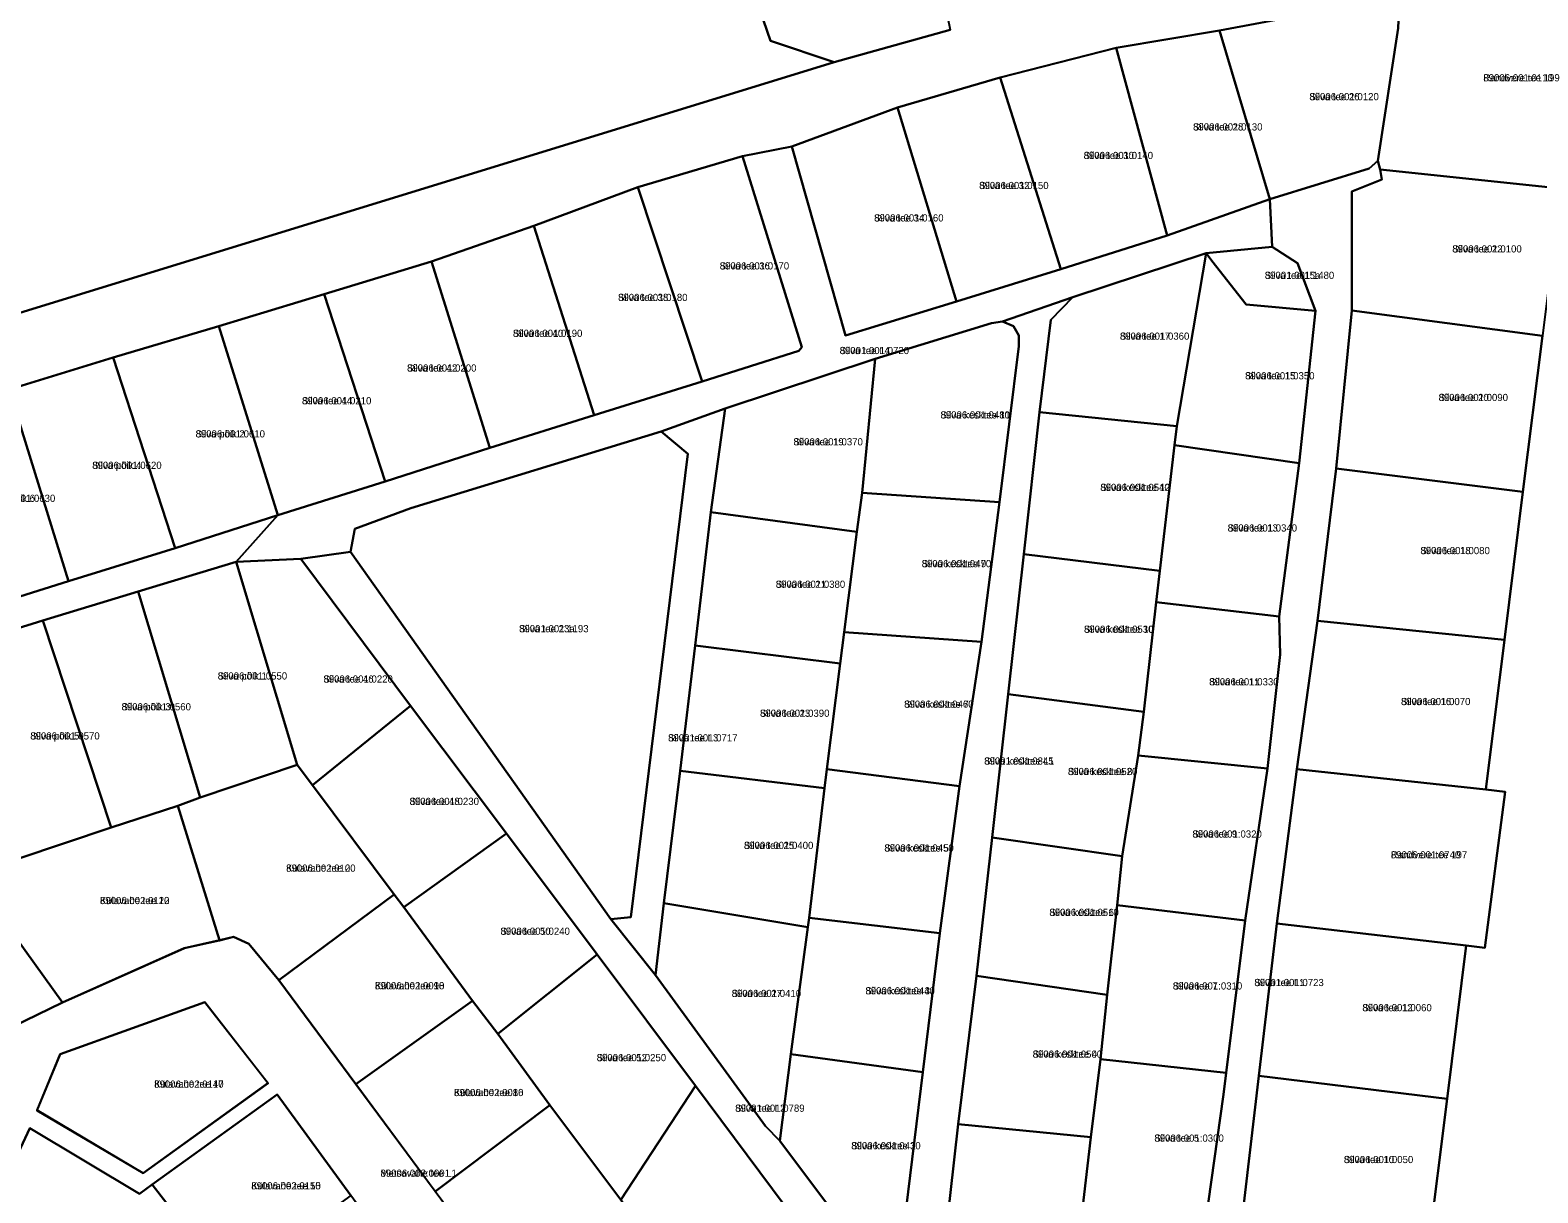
# Model space of a CAD drawing. Extents: x 526849 to 562296, y 6591741 to 6618546.
# Drawn here: x 550900.4 to 551215.3, y 6596298.2 to 6596541 of the extents above; entities that cross this region are included whole.
import ezdxf

# ---------------------------------------------------------------- set-up
doc = ezdxf.new("R2010")
doc.units = 0
for name, color, linetype in [('L_AADRESS', 7, 'Continuous'), ('PIIR', 7, 'Continuous'), ('TUNNUS', 7, 'Continuous')]:
    doc.layers.add(name, color=color, linetype=linetype)

msp = doc.modelspace()

# ---------------------------------------------------------------- linework, layer by layer
at = {"layer": 'PIIR'}
for points in [[(550502.84, 6596513.86), (550540.75, 6596522.24), (550580.98, 6596531.14), (550618.45, 6596539.43), (550657.91, 6596548.15), (550700.15, 6596557.5), (550724.96, 6596562.98), (550747.13, 6596567.89), (550790.4, 6596577.45), (550843.93, 6596589.29), (550876.6, 6596596.52), (550922.92, 6596606.76), (551006.9, 6596625.33), (551024.02, 6596629.12), (551028, 6596617.5), (551037.81, 6596588.91), (551046.33, 6596564.08), (551055.02, 6596538.73), (551068.28, 6596534.32), (550552.36, 6596375.52), (550533.68, 6596374.18), (550516.36, 6596378.66)], [(551046.33, 6596564.08), (551086.16, 6596571.97), (551092.5, 6596541.03), (551068.28, 6596534.32), (551055.02, 6596538.73)], [(551181.87, 6596513.7), (551186.1, 6596541.41), (551186.33, 6596547.98), (551225.89, 6596554.71), (551220.04, 6596507.9), (551182.35, 6596511.92)], [(551148.76, 6596540.93), (551186.33, 6596547.98), (551186.1, 6596541.41), (551181.87, 6596513.7), (551180.01, 6596512.11), (551159.29, 6596505.68)], [(551127.22, 6596537.3), (551148.76, 6596540.93), (551159.29, 6596505.68), (551137.82, 6596498.14)], [(551102.96, 6596531.08), (551127.22, 6596537.3), (551137.82, 6596498.14), (551115.63, 6596491.07)], [(551081.53, 6596524.81), (551102.96, 6596531.08), (551115.63, 6596491.07), (551093.86, 6596484.34)], [(551059.42, 6596516.7), (551081.53, 6596524.81), (551093.86, 6596484.34), (551070.69, 6596477.22)], [(551049.17, 6596514.64), (551059.42, 6596516.7), (551070.69, 6596477.22), (551093.86, 6596484.34), (551115.63, 6596491.07), (551137.82, 6596498.14), (551159.29, 6596505.68), (551159.79, 6596495.72), (551145.97, 6596494.4), (551118.15, 6596485.23), (551103.47, 6596480.15), (551101.15, 6596479.79), (551076.86, 6596472.34), (551045.55, 6596461.98), (551032.14, 6596457.18), (550979.88, 6596441.18), (550968.18, 6596436.89), (550967.28, 6596432.04), (550956.94, 6596430.62), (550943.43, 6596429.98), (550952.14, 6596439.69), (550974.5, 6596446.77), (550996.41, 6596453.74), (551018.2, 6596460.61), (551040.74, 6596467.62), (551060.95, 6596474.04), (551061.53, 6596474.78)], [(551027.26, 6596508.23), (551049.17, 6596514.64), (551061.53, 6596474.78), (551060.95, 6596474.04), (551040.74, 6596467.62)], [(551176.38, 6596507.32), (551182.64, 6596509.8), (551182.35, 6596511.92), (551220.04, 6596507.9), (551216.21, 6596477.19), (551176.41, 6596482.46)], [(551005.59, 6596500.12), (551027.26, 6596508.23), (551040.74, 6596467.62), (551018.2, 6596460.61)], [(550984.22, 6596492.71), (551005.59, 6596500.12), (551018.2, 6596460.61), (550996.41, 6596453.74)], [(551139.87, 6596458.29), (551111.17, 6596461.22), (551113.52, 6596480.49), (551118.15, 6596485.23), (551145.97, 6596494.4)], [(551139.87, 6596458.29), (551145.97, 6596494.4), (551147.19, 6596492.82), (551154.31, 6596483.69), (551168.84, 6596482.36), (551165.4, 6596450.57), (551139.4, 6596454.36)], [(551165.07, 6596492.36), (551168.84, 6596482.36), (551154.31, 6596483.69), (551147.19, 6596492.82), (551145.97, 6596494.4), (551159.79, 6596495.72)], [(550961.78, 6596485.84), (550984.22, 6596492.71), (550996.41, 6596453.74), (550974.5, 6596446.77)], [(550939.77, 6596479.14), (550961.78, 6596485.84), (550974.5, 6596446.77), (550952.14, 6596439.69)], [(551088.82, 6596266.44), (551081.09, 6596276.84), (551086.78, 6596323.41), (551090.37, 6596352.42), (551094.47, 6596383.11), (551099.07, 6596413.26), (551102.79, 6596442.45), (551106.83, 6596474.98), (551106.84, 6596477.21), (551105.78, 6596479.14), (551103.47, 6596480.15), (551118.15, 6596485.23), (551113.52, 6596480.49), (551111.17, 6596461.22), (551107.89, 6596431.54), (551104.66, 6596402.32), (551101.26, 6596372.44), (551098.05, 6596343.54), (551094.2, 6596312.54), (551090.95, 6596283.39), (551090.58, 6596281.58)], [(551176.41, 6596482.46), (551216.21, 6596477.19), (551212.14, 6596444.61), (551173.15, 6596449.44)], [(550917.7, 6596472.6), (550939.77, 6596479.14), (550952.14, 6596439.69), (550930.68, 6596432.81)], [(551101.15, 6596479.79), (551103.47, 6596480.15), (551105.78, 6596479.14), (551106.84, 6596477.21), (551106.83, 6596474.98), (551102.79, 6596442.45), (551074.16, 6596444.38), (551076.86, 6596472.34)], [(550896.01, 6596465.94), (550917.7, 6596472.6), (550930.68, 6596432.81), (550908.36, 6596425.95)], [(551045.55, 6596461.98), (551076.86, 6596472.34), (551074.16, 6596444.38), (551073.02, 6596436.22), (551042.52, 6596440.34)], [(550873.91, 6596459.07), (550896.01, 6596465.94), (550908.36, 6596425.95), (550886.67, 6596419.12)], [(551032.14, 6596457.18), (551045.55, 6596461.98), (551042.52, 6596440.34), (551039.26, 6596412.53), (551036.13, 6596386.31), (551032.74, 6596358.73), (551031, 6596343.64), (551021.67, 6596355.39), (551025.83, 6596355.76), (551037.71, 6596452.53)], [(551107.89, 6596431.54), (551111.17, 6596461.22), (551139.87, 6596458.29), (551139.4, 6596454.36), (551136.29, 6596428.1)], [(551025.83, 6596355.76), (551021.67, 6596355.39), (550967.28, 6596432.04), (550968.18, 6596436.89), (550979.88, 6596441.18), (551032.14, 6596457.18), (551037.71, 6596452.53)], [(551161.21, 6596418.58), (551135.55, 6596421.56), (551136.29, 6596428.1), (551139.4, 6596454.36), (551165.4, 6596450.57)], [(551173.15, 6596449.44), (551212.14, 6596444.61), (551208.28, 6596413.69), (551169.24, 6596417.68)], [(551099.07, 6596413.26), (551070.37, 6596415.28), (551073.02, 6596436.22), (551074.16, 6596444.38), (551102.79, 6596442.45)], [(550943.43, 6596429.98), (550922.93, 6596423.75), (550903.03, 6596417.71), (550883.52, 6596411.68), (550864.45, 6596405.6), (550830.39, 6596395.11), (550838.18, 6596371.91), (550838.2, 6596364.32), (550830.73, 6596370.47), (550822.31, 6596394.91), (550820.95, 6596398.4), (550825.97, 6596400.03), (550842.82, 6596405.22), (550864.71, 6596411.95), (550886.67, 6596419.12), (550908.36, 6596425.95), (550930.68, 6596432.81), (550952.14, 6596439.69)], [(551042.52, 6596440.34), (551073.02, 6596436.22), (551070.37, 6596415.28), (551069.54, 6596408.73), (551039.26, 6596412.53)], [(551134.17, 6596193.13), (551123.33, 6596207.83), (551104.41, 6596233.29), (551085.18, 6596259), (551066.23, 6596284.49), (551039.33, 6596320.56), (551018.77, 6596347.97), (550999.86, 6596373.25), (550979.83, 6596399.91), (550956.94, 6596430.62), (550967.28, 6596432.04), (551021.67, 6596355.39), (551031, 6596343.64), (551053.96, 6596312.14), (551056.93, 6596309.07), (551081.09, 6596276.84), (551088.82, 6596266.44), (551111.95, 6596235.1), (551120.32, 6596223.51), (551138.3, 6596224.47)], [(551104.66, 6596402.32), (551107.89, 6596431.54), (551136.29, 6596428.1), (551135.55, 6596421.56), (551132.96, 6596398.68)], [(550922.93, 6596423.75), (550943.43, 6596429.98), (550956.17, 6596387.56), (550935.88, 6596380.75)], [(550956.17, 6596387.56), (550943.43, 6596429.98), (550956.94, 6596430.62), (550979.83, 6596399.91), (550959.35, 6596383.32)], [(550903.03, 6596417.71), (550922.93, 6596423.75), (550935.88, 6596380.75), (550931.24, 6596379.03), (550917.28, 6596374.5)], [(551161.43, 6596410.59), (551158.81, 6596386.84), (551131.78, 6596389.55), (551132.96, 6596398.68), (551135.55, 6596421.56), (551161.21, 6596418.58)], [(550883.52, 6596411.68), (550903.03, 6596417.71), (550917.28, 6596374.5), (550897.8, 6596367.96)], [(551169.24, 6596417.68), (551208.28, 6596413.69), (551204.38, 6596382.42), (551164.9, 6596386.71)], [(551039.26, 6596412.53), (551069.54, 6596408.73), (551066.76, 6596386.71), (551066.25, 6596382.68), (551036.13, 6596386.31)], [(551094.47, 6596383.11), (551066.76, 6596386.71), (551069.54, 6596408.73), (551070.37, 6596415.28), (551099.07, 6596413.26)], [(550976.43, 6596360.53), (550959.35, 6596383.32), (550979.83, 6596399.91), (550999.86, 6596373.25), (550978.43, 6596357.83)], [(551104.66, 6596402.32), (551132.96, 6596398.68), (551131.78, 6596389.55), (551128.44, 6596368.53), (551101.26, 6596372.44)], [(550956.17, 6596387.56), (550959.35, 6596383.32), (550976.43, 6596360.53), (550952.34, 6596342.65), (550946.05, 6596350.22), (550942.86, 6596351.69), (550939.92, 6596350.94), (550931.24, 6596379.03), (550935.88, 6596380.75)], [(551154.15, 6596355.05), (551127.4, 6596358.25), (551128.44, 6596368.53), (551131.78, 6596389.55), (551158.81, 6596386.84)], [(551036.13, 6596386.31), (551066.25, 6596382.68), (551063.08, 6596355.65), (551062.79, 6596353.71), (551032.74, 6596358.73)], [(551090.37, 6596352.42), (551063.08, 6596355.65), (551066.25, 6596382.68), (551066.76, 6596386.71), (551094.47, 6596383.11)], [(551204.38, 6596382.42), (551208.44, 6596381.96), (551204.16, 6596349.4), (551200.31, 6596349.87), (551160.77, 6596354.44), (551164.9, 6596386.71)], [(550931.24, 6596379.03), (550939.92, 6596350.94), (550932.57, 6596349.27), (550907.15, 6596337.96), (550887.9, 6596364.63), (550897.8, 6596367.96), (550917.28, 6596374.5)], [(550978.43, 6596357.83), (550999.86, 6596373.25), (551018.77, 6596347.97), (550998.07, 6596331.41), (550992.75, 6596338.3)], [(551098.05, 6596343.54), (551101.26, 6596372.44), (551128.44, 6596368.53), (551127.4, 6596358.25), (551125.3, 6596339.59)], [(550887.9, 6596364.63), (550907.15, 6596337.96), (550888.88, 6596329.1), (550870.76, 6596323.96), (550860.24, 6596355.35), (550878.68, 6596361.7)], [(550992.75, 6596338.3), (550968.4, 6596320.88), (550952.34, 6596342.65), (550976.43, 6596360.53), (550978.43, 6596357.83)], [(551053.96, 6596312.14), (551031, 6596343.64), (551032.74, 6596358.73), (551062.79, 6596353.71), (551059.27, 6596327.14), (551056.93, 6596309.07)], [(551090.37, 6596352.42), (551086.78, 6596323.41), (551059.27, 6596327.14), (551062.79, 6596353.71), (551063.08, 6596355.65)], [(551150.15, 6596323.24), (551123.89, 6596326.11), (551125.3, 6596339.59), (551127.4, 6596358.25), (551154.15, 6596355.05)], [(551160.77, 6596354.44), (551200.31, 6596349.87), (551196.31, 6596317.83), (551156.99, 6596322.63)], [(551018.77, 6596347.97), (551039.33, 6596320.56), (551023.76, 6596296.72), (551008.93, 6596316.55), (550998.07, 6596331.41)], [(551094.2, 6596312.54), (551098.05, 6596343.54), (551125.3, 6596339.59), (551123.89, 6596326.11), (551121.93, 6596309.83)], [(550906.66, 6596327.2), (550901.79, 6596315.41), (550924, 6596302.3), (550950.04, 6596321.13), (550936.86, 6596338.03)], [(550936.86, 6596338.04), (550950.08, 6596321.09), (550924.01, 6596302.3), (550901.81, 6596315.45), (550906.64, 6596327.19)], [(551008.93, 6596316.55), (550984.95, 6596298.52), (550968.4, 6596320.88), (550992.75, 6596338.3), (550998.07, 6596331.41)], [(551081.09, 6596276.84), (551056.93, 6596309.07), (551059.27, 6596327.14), (551086.78, 6596323.41)], [(551149.59, 6596318.78), (551145.77, 6596291.52), (551120.19, 6596294.88), (551121.93, 6596309.83), (551123.89, 6596326.11), (551150.15, 6596323.24)], [(551156.99, 6596322.63), (551196.31, 6596317.83), (551192.37, 6596286.22), (551153.2, 6596290.55)], [(550806.79, 6596277.8), (550806.2, 6596260.48), (550850.99, 6596252.41), (550884.4, 6596246.39), (550914.38, 6596240.89), (550917.47, 6596238.7), (550925.48, 6596233.16), (550958.22, 6596256.98), (550983.56, 6596275.41), (550967.38, 6596297.69), (550951.96, 6596318.74), (550925.84, 6596299.94), (550923.21, 6596298.04), (550900.3, 6596311.7), (550897.38, 6596305.47), (550894.68, 6596306.3), (550885.81, 6596312.96), (550875.33, 6596310), (550842.72, 6596295.97)], [(550936.69, 6596285.88), (550925.87, 6596299.93), (550951.95, 6596318.75), (550967.38, 6596297.69), (550941.86, 6596279.11)], [(551023.76, 6596296.72), (551039.33, 6596320.56), (551066.23, 6596284.49), (551044.34, 6596268.92), (551026.95, 6596292.39)], [(551026.95, 6596292.39), (551002.78, 6596274.49), (550984.95, 6596298.52), (551008.93, 6596316.55), (551023.76, 6596296.72)], [(550842.72, 6596295.97), (550875.33, 6596310), (550885.81, 6596312.96), (550894.68, 6596306.3), (550897.38, 6596305.47), (550900.3, 6596311.7), (550923.21, 6596298.04), (550925.84, 6596299.94), (550936.69, 6596285.87), (550927.35, 6596279.09), (550890.53, 6596280.37), (550857.07, 6596285.92)], [(551090.95, 6596283.39), (551094.2, 6596312.54), (551121.93, 6596309.83), (551120.19, 6596294.88), (551118.49, 6596279.69)]]:
    msp.add_lwpolyline(points, close=True, dxfattribs=at)
for points in [[(551186.33, 6596547.98), (551148.76, 6596540.93), (551127.22, 6596537.3), (551102.96, 6596531.08), (551081.53, 6596524.81), (551059.42, 6596516.7), (551049.17, 6596514.64), (551027.26, 6596508.23), (551005.59, 6596500.12), (550984.22, 6596492.71), (550961.78, 6596485.84), (550939.77, 6596479.14), (550917.7, 6596472.6), (550896.01, 6596465.94), (550873.91, 6596459.07), (550851.8, 6596452.33), (550829.76, 6596445.49), (550807.86, 6596438.64), (550784.34, 6596431.16), (550695.5, 6596403.25), (550540.54, 6596354.46)], [(550552.36, 6596375.52), (551068.28, 6596534.32), (551092.5, 6596541.03)], [(551145.77, 6596291.52), (551149.59, 6596318.78), (551150.15, 6596323.24), (551154.15, 6596355.05), (551158.81, 6596386.84), (551161.43, 6596410.59), (551161.21, 6596418.58), (551165.4, 6596450.57), (551168.84, 6596482.36), (551165.07, 6596492.36), (551159.79, 6596495.72), (551159.29, 6596505.68), (551180.01, 6596512.11), (551181.87, 6596513.7), (551182.35, 6596511.92), (551182.64, 6596509.8), (551176.38, 6596507.32), (551176.41, 6596482.46), (551173.15, 6596449.44), (551169.24, 6596417.68), (551164.9, 6596386.71), (551160.77, 6596354.44), (551156.99, 6596322.63), (551153.2, 6596290.55)], [(551157.47, 6596029.7), (551165.04, 6596077.7), (551168.89, 6596078.24), (551171.19, 6596097.74), (551168.74, 6596101.05), (551156.07, 6596118.25), (551148.73, 6596128.3), (551155, 6596133.16), (551172.69, 6596128.6), (551180.25, 6596189.15), (551184.46, 6596222.92), (551188.41, 6596254.51), (551192.37, 6596286.22), (551196.31, 6596317.83), (551200.31, 6596349.87), (551204.16, 6596349.4), (551208.44, 6596381.96), (551204.38, 6596382.42), (551208.28, 6596413.69), (551212.14, 6596444.61), (551216.21, 6596477.19)], [(550888.88, 6596329.1), (550907.15, 6596337.96), (550932.58, 6596349.28), (550939.91, 6596350.93), (550942.86, 6596351.69), (550946.04, 6596350.21), (550952.34, 6596342.65), (550968.41, 6596320.88), (550984.94, 6596298.54), (551002.76, 6596274.5)]]:
    msp.add_lwpolyline(points, dxfattribs=at)

# ---------------------------------------------------------------- texts
at = {"layer": 'L_AADRESS'}
for s, p in [('Randvere tee 199', (551203.88, 6596530.29)), ('Silva tee 26', (551167.54, 6596526.35)), ('Silva tee 28', (551143.25, 6596520.03)), ('Silva tee 30', (551120.39, 6596514.07)), ('Silva tee 32', (551098.58, 6596507.8)), ('Silva tee 34', (551076.64, 6596501.03)), ('Silva tee 22', (551197.39, 6596494.56)), ('Silva tee 36', (551044.39, 6596491.01)), ('Silva tee 15a', (551158.23, 6596489.04)), ('Silva tee 38', (551023.17, 6596484.43)), ('Silva tee 40', (551001.21, 6596476.93)), ('Silva tee 17', (551127.97, 6596476.34)), ('Silva tee L4', (551069.43, 6596473.34)), ('Silva tee 42', (550979.09, 6596469.69)), ('Silva tee 15', (551154.12, 6596468.07)), ('Silva tee 44', (550957.14, 6596462.85)), ('Silva tee 20', (551194.52, 6596463.54)), ('Silva kesktee 11', (551090.5, 6596459.9)), ('Silva põik 2', (550934.92, 6596455.94)), ('Silva tee 19', (551059.79, 6596454.28)), ('Silva põik 4', (550913.34, 6596449.37)), ('Silva põik 6', (550891.13, 6596442.48)), ('Silva kesktee 12', (551123.88, 6596444.76)), ('Silva tee 13', (551150.47, 6596436.29)), ('Silva tee 18', (551190.73, 6596431.57)), ('Silva kesktee 9', (551086.58, 6596428.84)), ('Silva tee 21', (551056.1, 6596424.54)), ('Silva tee 23a', (551002.5, 6596415.26)), ('Silva kesktee 10', (551120.47, 6596415.15)), ('Silva põik 1', (550939.55, 6596405.39)), ('Silva tee 46', (550961.63, 6596404.75)), ('Silva tee 11', (551146.61, 6596404.17)), ('Silva põik 3', (550919.46, 6596398.95)), ('Silva kesktee 7', (551082.91, 6596399.5)), ('Silva tee 16', (551186.67, 6596400.05)), ('Silva tee 23', (551052.81, 6596397.61)), ('Silva põik 5', (550900.4, 6596392.87)), ('Silva tee L3', (551033.61, 6596392.47)), ('Silva kesktee L1', (551099.62, 6596387.63)), ('Silva kesktee 8', (551117.11, 6596385.44)), ('Silva tee 48', (550979.61, 6596379.2)), ('Silva tee 25', (551049.45, 6596370.01)), ('Silva tee 9', (551143.11, 6596372.39)), ('Silva kesktee 5', (551078.77, 6596369.47)), ('Randvere tee 197', (551184.56, 6596368.05)), ('Külavahe tee 20', (550953.84, 6596365.27)), ('Külavahe tee 22', (550914.96, 6596358.5)), ('Silva kesktee 6', (551113.24, 6596356.03)), ('Silva tee 50', (550998.6, 6596352.09)), ('Külavahe tee 18', (550972.38, 6596340.71)), ('Silva tee 27', (551046.89, 6596339.1)), ('Silva kesktee 3', (551074.82, 6596339.65)), ('Silva tee 7', (551139.02, 6596340.66)), ('Silva tee L1', (551156.05, 6596341.38)), ('Silva tee 12', (551178.6, 6596336.13)), ('Silva kesktee 4', (551109.75, 6596326.43)), ('Silva tee 52', (551018.7, 6596325.7)), ('Külavahe tee 17', (550926.28, 6596320.17)), ('Külavahe tee 16', (550988.9, 6596318.41)), ('Silva tee L2', (551047.62, 6596315.14)), ('Silva kesktee 1', (551071.86, 6596307.3)), ('Silva tee 5', (551135.17, 6596308.89)), ('Silva tee 10', (551174.74, 6596304.42)), ('Metsavahe tee L1', (550973.55, 6596301.57)), ('Külavahe tee 15', (550946.56, 6596298.93))]:
    msp.add_text(s, height=1.5, dxfattribs=at).set_placement(p)
at = {"layer": 'TUNNUS'}
for s, p in [('89006:001:0110', (551203.88, 6596530.29)), ('89006:001:0120', (551167.54, 6596526.35)), ('89006:001:0130', (551143.25, 6596520.03)), ('89006:001:0140', (551120.39, 6596514.07)), ('89006:001:0150', (551098.58, 6596507.8)), ('89006:001:0160', (551076.64, 6596501.03)), ('89006:001:0100', (551197.39, 6596494.56)), ('89006:001:0170', (551044.39, 6596491.01)), ('89001:001:1480', (551158.23, 6596489.04)), ('89006:001:0180', (551023.17, 6596484.43)), ('89006:001:0190', (551001.21, 6596476.93)), ('89006:001:0360', (551127.97, 6596476.34)), ('89001:001:0720', (551069.43, 6596473.34)), ('89006:001:0200', (550979.09, 6596469.69)), ('89006:001:0350', (551154.12, 6596468.07)), ('89006:001:0210', (550957.14, 6596462.85)), ('89006:001:0090', (551194.52, 6596463.54)), ('89006:001:0480', (551090.5, 6596459.9)), ('89006:001:0610', (550934.92, 6596455.94)), ('89006:001:0370', (551059.79, 6596454.28)), ('89006:001:0620', (550913.34, 6596449.37)), ('89006:001:0630', (550891.13, 6596442.48)), ('89006:001:0540', (551123.88, 6596444.76)), ('89006:001:0340', (551150.47, 6596436.29)), ('89006:001:0080', (551190.73, 6596431.57)), ('89006:001:0470', (551086.58, 6596428.84)), ('89006:001:0380', (551056.1, 6596424.54)), ('89001:001:1193', (551002.5, 6596415.26)), ('89006:001:0530', (551120.47, 6596415.15)), ('89006:001:0550', (550939.55, 6596405.39)), ('89006:001:0220', (550961.63, 6596404.75)), ('89006:001:0330', (551146.61, 6596404.17)), ('89006:001:0560', (550919.46, 6596398.95)), ('89006:001:0460', (551082.91, 6596399.5)), ('89006:001:0070', (551186.67, 6596400.05)), ('89006:001:0390', (551052.81, 6596397.61)), ('89006:001:0570', (550900.4, 6596392.87)), ('89001:001:0717', (551033.61, 6596392.47)), ('89001:001:0845', (551099.62, 6596387.63)), ('89006:001:0520', (551117.11, 6596385.44)), ('89006:001:0230', (550979.61, 6596379.2)), ('89006:001:0400', (551049.45, 6596370.01)), ('89006:001:0320', (551143.11, 6596372.39)), ('89006:001:0450', (551078.77, 6596369.47)), ('89006:001:0740', (551184.56, 6596368.05)), ('89006:002:0100', (550953.84, 6596365.27)), ('89006:002:0110', (550914.96, 6596358.5)), ('89006:001:0510', (551113.24, 6596356.03)), ('89006:001:0240', (550998.6, 6596352.09)), ('89006:002:0090', (550972.38, 6596340.71)), ('89006:001:0410', (551046.89, 6596339.1)), ('89006:001:0440', (551074.82, 6596339.65)), ('89006:001:0310', (551139.02, 6596340.66)), ('89001:001:0723', (551156.05, 6596341.38)), ('89006:001:0060', (551178.6, 6596336.13)), ('89006:001:0500', (551109.75, 6596326.43)), ('89006:001:0250', (551018.7, 6596325.7)), ('89006:002:0140', (550926.28, 6596320.17)), ('89006:002:0080', (550988.9, 6596318.41)), ('89001:001:0789', (551047.62, 6596315.14)), ('89006:001:0430', (551071.86, 6596307.3)), ('89006:001:0300', (551135.17, 6596308.89)), ('89006:001:0050', (551174.74, 6596304.42)), ('89006:002:0001', (550973.55, 6596301.57)), ('89006:002:0150', (550946.56, 6596298.93))]:
    msp.add_text(s, height=1.5, dxfattribs=at).set_placement(p)

doc.saveas('drawing.dxf')
